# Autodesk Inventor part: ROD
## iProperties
Shininess: 64.0
Length Units: 11269
Angle Units: 11279
Time Units: 11290
Mass Units: 11283
Length Display Precision: 3
Angle Display Precision: 2
Compacted: True
Part Number: ROD
Document SubType Name: Modeling
Created: 2004-05
Designer: Daniel
Manufacturer: Standard
Standards Organization: Custom
Density: 0.0
Volumn: 0.0
Area: 0.0
PropertySet Name: Model Information
Control State: 0
Master: False
Checked Out: False
Author: Daniel
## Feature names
1. Extrusion1
2. Extrusion2
3. Extrusion3
4. Extrusion4
5. Extrusion5
